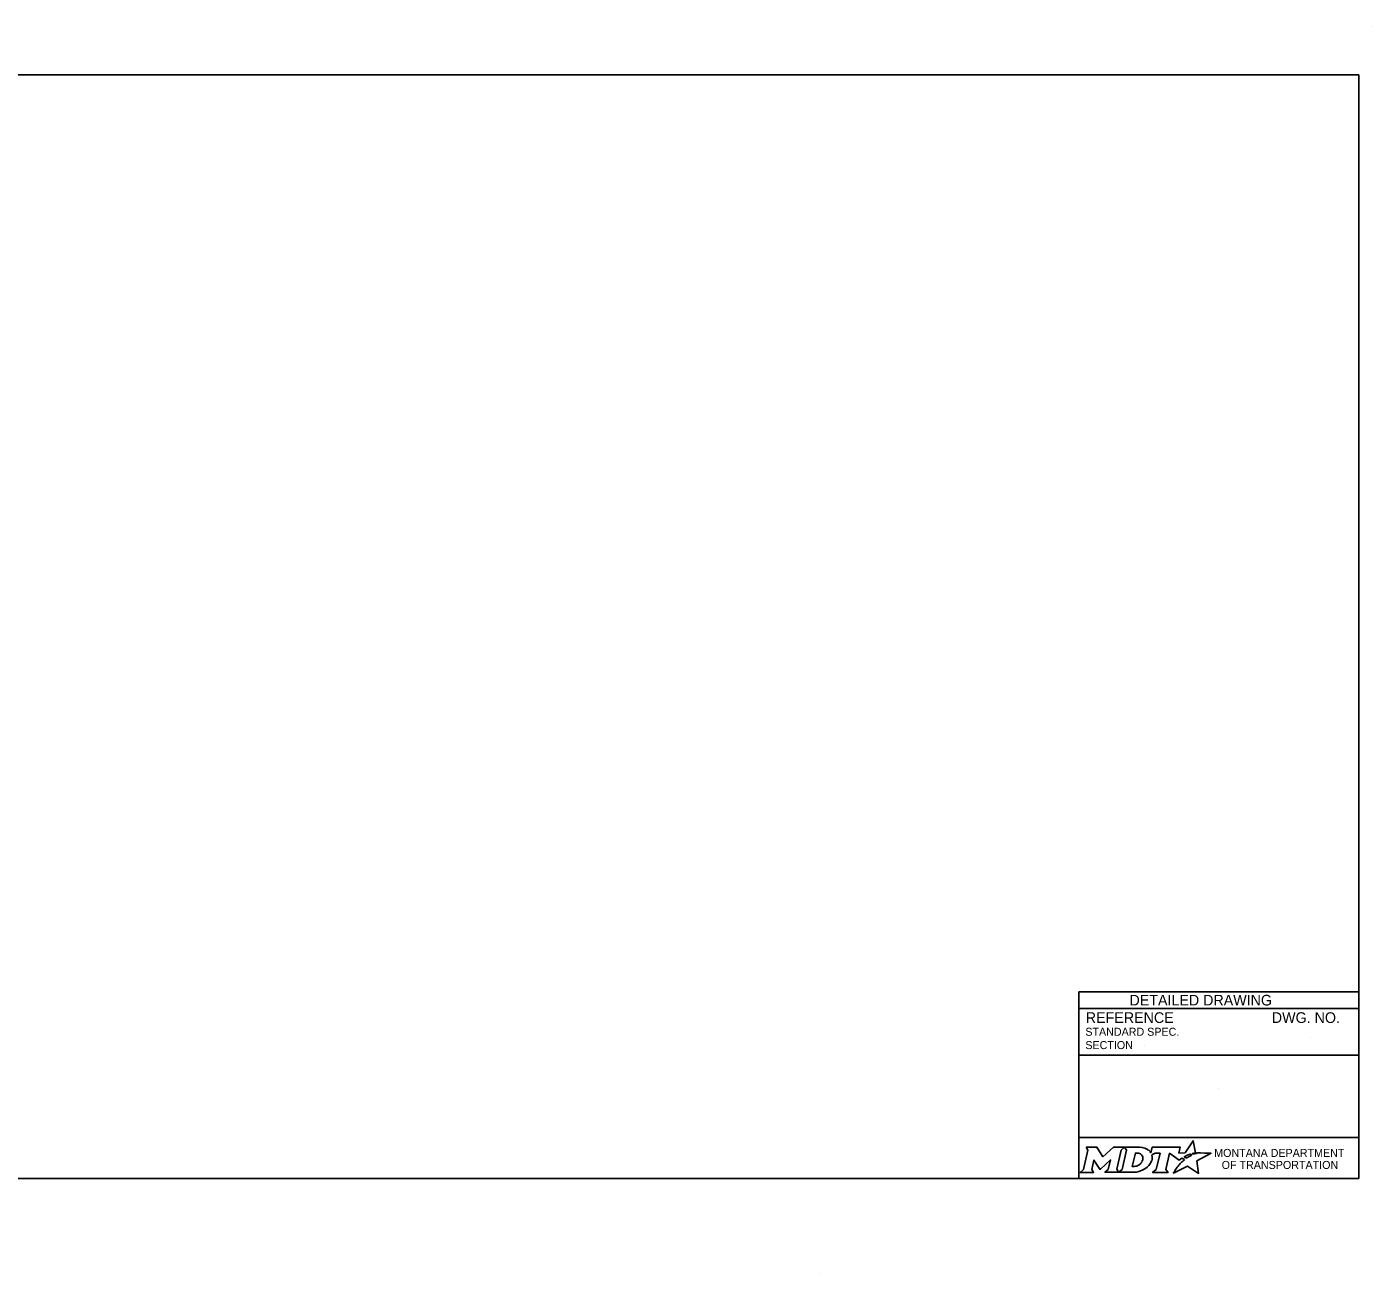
# Model space of a CAD drawing. Extents: x 49991.4 to 50021, y 49987.6 to 50011.4.
# Drawn here: x 50010.95 to 50021.04, y 49999.18 to 50008.52 of the extents above; entities that cross this region are included whole.
import ezdxf

# ---------------------------------------------------------------- set-up
doc = ezdxf.new("R2010")
doc.units = 0
for name, color, linetype in [('Default', 7, 'Continuous'), ('Level 1', 7, 'Continuous'), ('Level 4', 7, 'Continuous')]:
    doc.layers.add(name, color=color, linetype=linetype)

msp = doc.modelspace()

# ---------------------------------------------------------------- linework, layer by layer
at = {"layer": 'Default'}
for points in [[(50019.7, 50000.068), (50019.69, 50000.074), (50019.702, 50000.076), (50019.713, 50000.078), (50019.696, 50000.168), (50019.636, 50000.077), (50019.589, 50000.076), (50019.599, 50000.12), (50019.39, 50000.121), (50019.38, 50000.078), (50019.374, 50000.086)], [(50018.893, 50000.121), (50018.907, 50000.097), (50018.874, 49999.954), (50018.848, 49999.931), (50018.95, 49999.931), (50018.936, 49999.954), (50018.952, 50000.024), (50018.996, 49999.955), (50019.002, 49999.955), (50019.077, 50000.025), (50019.06, 49999.954), (50019.035, 49999.932), (50019.137, 49999.932), (50019.123, 49999.955), (50019.156, 50000.097)], [(50019.156, 50000.097), (50019.182, 50000.121), (50019.099, 50000.121), (50019.02, 50000.048), (50018.975, 50000.12), (50018.893, 50000.121)], [(50019.295, 50000.121), (50019.182, 50000.121), (50019.196, 50000.098), (50019.163, 49999.954), (50019.137, 49999.932), (50019.248, 49999.932)], [(50019.319, 50000.034), (50019.318, 50000.026), (50019.315, 50000.017), (50019.311, 50000.008), (50019.305, 50000.001), (50019.299, 49999.994), (50019.291, 49999.988), (50019.282, 49999.983), (50019.273, 49999.979), (50019.264, 49999.977), (50019.255, 49999.976), (50019.239, 49999.976), (50019.263, 50000.076), (50019.279, 50000.076), (50019.286, 50000.075), (50019.294, 50000.073), (50019.301, 50000.07), (50019.307, 50000.066), (50019.311, 50000.061), (50019.315, 50000.055), (50019.318, 50000.049), (50019.319, 50000.042), (50019.32, 50000.038), (50019.319, 50000.034)], [(50019.387, 50000.062), (50019.411, 50000.075), (50019.448, 50000.075), (50019.42, 49999.954), (50019.392, 49999.931), (50019.508, 49999.931), (50019.491, 49999.954), (50019.52, 50000.075), (50019.591, 50000.023), (50019.612, 50000.038), (50019.632, 50000.027)], [(50019.576, 49999.971), (50019.561, 49999.947), (50019.556, 49999.939), (50019.55, 49999.931), (50019.548, 49999.926), (50019.653, 49999.979), (50019.737, 49999.924), (50019.724, 50000.017), (50019.831, 50000.075), (50019.782, 50000.076), (50019.751, 50000.077), (50019.731, 50000.077), (50019.724, 50000.075), (50019.719, 50000.074), (50019.711, 50000.072), (50019.7, 50000.068)], [(50019.65, 50000.04), (50019.648, 50000.039), (50019.629, 50000.048), (50019.639, 50000.054), (50019.644, 50000.056), (50019.652, 50000.06), (50019.658, 50000.063), (50019.666, 50000.066), (50019.673, 50000.068), (50019.685, 50000.061), (50019.681, 50000.059), (50019.676, 50000.056), (50019.672, 50000.054), (50019.667, 50000.051), (50019.665, 50000.05), (50019.662, 50000.049), (50019.66, 50000.047), (50019.658, 50000.046), (50019.655, 50000.044), (50019.652, 50000.042), (50019.65, 50000.04)], [(50019.293, 49999.939), (50019.302, 49999.942), (50019.315, 49999.947), (50019.335, 49999.958)], [(50019.59, 49999.987), (50019.59, 49999.987)]]:
    msp.add_lwpolyline(points, dxfattribs=at)
for centre, radius, start, end in [((50019.319, 50000.042), 0.0709, 339.5329, 15.8582), ((50019.274, 50000.059), 0.118, 300.9103, 339.1383)]:
    msp.add_arc(centre, radius, start, end, dxfattribs=at)
for centre, major_axis, ratio, start_param, end_param in [((50019.293, 50000.073), (0.0834, -0.0037), 0.568097, 0.61298, 1.570796), ((50019.349, 50000.081), (0.0361, -0.0295), 0.469099, 1.225588, 1.570796), ((50019.248, 50000.08), (0, 0.148), 0.987302, 3.139398, 3.456847), ((50019.583, 49999.979), (-0.00694, -0.00806), 0.008222, 0, 3.137361), ((50019.6, 49999.997), (-0.0098, -0.0102), 0.016458, 3.141593, 6.279097), ((50019.621, 50000.017), (-0.0112, -0.0097), 0.021651, 3.157348, 6.283185)]:
    msp.add_ellipse(centre, major_axis=major_axis, ratio=ratio, start_param=start_param, end_param=end_param, dxfattribs=at)
at = {"layer": 'Level 1'}
for p, q in [((50021.038, 50008.524), (50021.038, 50008.524)), ((50016.9, 49999.176), (50016.9, 49999.176))]:
    msp.add_line(p, q, dxfattribs=at)
msp.add_lwpolyline([(50020.938, 50008.165), (50009.737, 50008.165), (50009.737, 49999.886), (50020.938, 49999.886)], close=True, dxfattribs=at)
at = {"layer": 'Level 4'}
for p, q in [((50020.938, 50001.286), (50018.838, 50001.286)), ((50018.838, 50001.286), (50018.838, 49999.886)), ((50020.938, 50001.161), (50018.838, 50001.161)), ((50020.574, 50000.946), (50020.574, 50000.946)), ((50019.332, 50000.886), (50019.332, 50000.886)), ((50020.938, 50000.811), (50018.838, 50000.811)), ((50019.888, 50000.562), (50019.888, 50000.562)), ((50020.938, 50000.193), (50018.838, 50000.193))]:
    msp.add_line(p, q, dxfattribs=at)

# ---------------------------------------------------------------- texts
at = {"layer": 'Default'}
for s, p in [('MONTANA DEPARTMENT', (50019.854, 50000.047)), ('OF TRANSPORTATION', (50019.91, 49999.957))]:
    msp.add_text(s, height=0.06, dxfattribs=at).set_placement(p)
at = {"layer": 'Level 4'}
for s, height, p in [('DETAILED DRAWING', 0.0799, (50019.219, 50001.183)), ('REFERENCE', 0.08, (50018.891, 50001.052)), ('DWG. NO.', 0.08, (50020.286, 50001.052)), ('STANDARD SPEC.', 0.06, (50018.888, 50000.956)), ('SECTION', 0.06, (50018.888, 50000.856))]:
    msp.add_text(s, height=height, dxfattribs=at).set_placement(p)

doc.saveas('drawing.dxf')
